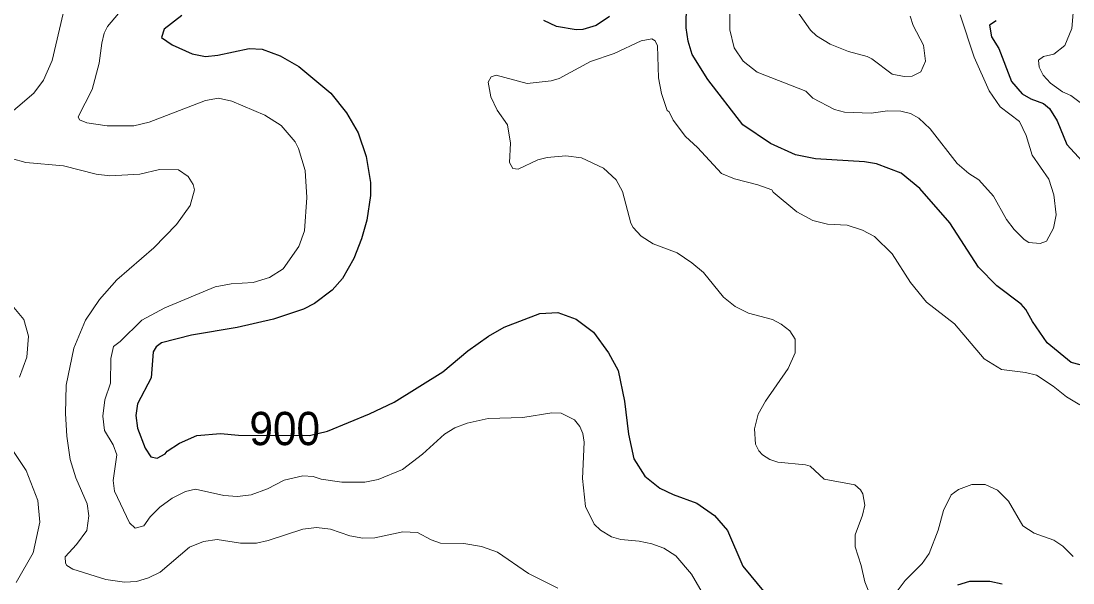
# Model space of a CAD drawing. Extents: x 265 to 291.4, y 7731.5 to 7759.6.
# Drawn here: x 287.145 to 289.671, y 7738.754 to 7740.103 of the extents above; entities that cross this region are included whole.
import ezdxf
from ezdxf.enums import TextEntityAlignment as Align

# ---------------------------------------------------------------- set-up
doc = ezdxf.new("R2010")
doc.units = 0
doc.header["$LTSCALE"] = 0.032
for name, color, linetype, lineweight in [('1', 7, 'Continuous', 25), ('2', 7, 'Continuous', 13), ('61', 7, 'Continuous', 13)]:
    doc.layers.add(name, color=color, linetype=linetype, lineweight=lineweight)

msp = doc.modelspace()

# ---------------------------------------------------------------- linework, layer by layer
at = {"layer": '1'}
for points in [[(289.3759, 7739.619), (289.3035, 7739.701), (289.259, 7739.7383), (289.1993, 7739.7606), (289.1707, 7739.7654), (289.053, 7739.7725), (289.0052, 7739.7821), (288.9448, 7739.8091), (288.8787, 7739.8545), (288.7944, 7739.9627), (288.757, 7740.0231), (288.7475, 7740.055), (288.7427, 7740.0868), (288.7435, 7740.1457)], [(287.5312, 7740.117), (287.489, 7740.0836), (287.4827, 7740.0637), (287.5081, 7740.0462), (287.5559, 7740.0247), (287.5877, 7740.0183), (287.6179, 7740.0215), (287.6927, 7740.0374), (287.7245, 7740.0358), (287.7675, 7740.0199), (287.812, 7739.9945), (287.8891, 7739.9301), (287.9265, 7739.8831), (287.9544, 7739.8354), (287.9743, 7739.7781), (287.9846, 7739.7161), (287.9846, 7739.6843), (287.9759, 7739.6254), (287.9631, 7739.5809), (287.944, 7739.5331), (287.917, 7739.4854), (287.8923, 7739.4575), (287.8502, 7739.4249), (287.8231, 7739.4114), (287.7516, 7739.3875), (287.664, 7739.3676), (287.5543, 7739.3493), (287.4827, 7739.331), (287.4699, 7739.3215), (287.462, 7739.3096), (287.4572, 7739.2468), (287.4246, 7739.1847), (287.4206, 7739.1561), (287.4246, 7739.1258), (287.4429, 7739.0781), (287.4564, 7739.0574), (287.4723, 7739.0542), (287.4914, 7739.0646), (287.4962, 7739.0709), (287.5256, 7739.09), (287.567, 7739.1083), (287.6243, 7739.1131), (287.6672, 7739.1091)], [(288.5581, 7740.1146), (288.5264, 7740.0931), (288.4945, 7740.0828), (288.4786, 7740.082), (288.4309, 7740.0907), (288.4007, 7740.1051)], [(289.4873, 7740.1043), (289.4706, 7740.0939), (289.4761, 7740.0653), (289.4936, 7740.0375), (289.5239, 7739.9579), (289.5493, 7739.9285), (289.57, 7739.9165), (289.6003, 7739.9054), (289.6154, 7739.8935), (289.6336, 7739.8641), (289.6567, 7739.8068), (289.7116, 7739.7471)], [(289.6098, 7739.3311), (289.574, 7739.382), (289.5581, 7739.4106), (289.5469, 7739.4233), (289.4889, 7739.4679), (289.4443, 7739.5124), (289.3759, 7739.619)], [(288.2177, 7739.312), (288.2678, 7739.347), (288.3052, 7739.3684), (288.3911, 7739.4011), (288.4341, 7739.4034), (288.4786, 7739.3875), (288.52, 7739.3565), (288.5558, 7739.3072), (288.5788, 7739.2643), (288.5947, 7739.1911), (288.6043, 7739.1115), (288.617, 7739.0527), (288.6433, 7739.0105), (288.6791, 7738.9818), (288.7109, 7738.9667), (288.7682, 7738.946), (288.8103, 7738.9166), (288.8421, 7738.88), (288.8787, 7738.7949), (288.932, 7738.7297)], [(289.71, 7739.2722), (289.6671, 7739.2833), (289.6098, 7739.3311)], [(287.6672, 7739.1091), (287.8375, 7739.1086), (287.8812, 7739.1186), (287.9822, 7739.16), (288.0411, 7739.1887), (288.158, 7739.261), (288.2177, 7739.312)], [(289.395, 7738.7496), (289.4237, 7738.7583), (289.4714, 7738.7583), (289.5016, 7738.7519)]]:
    msp.add_lwpolyline(points, dxfattribs=at)
at = {"layer": '2'}
for points in [[(287.3252, 7739.736), (287.2472, 7739.7559), (287.1565, 7739.7638), (287.0865, 7739.7829), (287.065, 7739.7956), (287.0547, 7739.8076), (287.0515, 7739.8211), (287.0539, 7739.8274), (287.1756, 7739.9301), (287.1987, 7739.9611), (287.2201, 7740.0088), (287.2464, 7740.1218)], [(287.3793, 7740.1218), (287.353, 7740.09), (287.345, 7740.0741), (287.3387, 7740.0502), (287.3323, 7740.0025), (287.3156, 7739.9388), (287.2822, 7739.8736), (287.2854, 7739.8664), (287.3029, 7739.8593), (287.3522, 7739.8521), (287.4159, 7739.8521), (287.4524, 7739.8609), (287.5877, 7739.9126), (287.6195, 7739.9181), (287.6513, 7739.911), (287.7309, 7739.8776), (287.7698, 7739.8529), (287.8032, 7739.8131), (287.8112, 7739.7972), (287.8271, 7739.7447), (287.8311, 7739.6795), (287.8255, 7739.5999), (287.812, 7739.5618), (287.7746, 7739.5085), (287.742, 7739.4878), (287.7022, 7739.4758), (287.6497, 7739.4727), (287.6115, 7739.4655), (287.4906, 7739.4146), (287.4349, 7739.3852), (287.3832, 7739.3343), (287.3673, 7739.3223), (287.361, 7739.2929), (287.3602, 7739.234)], [(289.2812, 7739.8815), (289.2582, 7739.8871), (289.2264, 7739.8879), (289.1866, 7739.8823), (289.123, 7739.8847), (289.0991, 7739.8911), (289.0466, 7739.9181), (289.0299, 7739.9348), (288.913, 7739.981), (288.8795, 7740.0072), (288.8581, 7740.0391), (288.8477, 7740.082), (288.8477, 7740.1297)], [(289.0108, 7740.125), (289.041, 7740.0812), (289.0553, 7740.0677), (289.088, 7740.0478), (289.1325, 7740.0303), (289.1771, 7740.0184), (289.1882, 7740.0128), (289.2375, 7739.9762), (289.2662, 7739.9706), (289.2852, 7739.9714), (289.3059, 7739.9818), (289.3171, 7740.0072), (289.3123, 7740.0454), (289.2876, 7740.0931), (289.2805, 7740.1154)], [(289.4006, 7740.1186), (289.434, 7740.0168), (289.4698, 7739.9356), (289.4968, 7739.8975), (289.543, 7739.8625), (289.5589, 7739.829), (289.5732, 7739.7813), (289.6138, 7739.724), (289.6257, 7739.6859), (289.6313, 7739.6381), (289.6249, 7739.6063), (289.6082, 7739.5753), (289.5923, 7739.5697), (289.5653, 7739.5721), (289.5541, 7739.5793), (289.5302, 7739.6031), (289.5119, 7739.627), (289.4809, 7739.6827)], [(289.7084, 7739.8927), (289.6663, 7739.9245), (289.6464, 7739.9332), (289.6177, 7739.9539), (289.6002, 7739.9738), (289.5899, 7739.9929), (289.5883, 7740.0096), (289.601, 7740.0184), (289.6257, 7740.0239), (289.652, 7740.0446), (289.6687, 7740.0852), (289.6718, 7740.1234)], [(289.1882, 7738.7154), (289.1715, 7738.7567), (289.1627, 7738.7965), (289.1484, 7738.8411), (289.1484, 7738.8697), (289.1659, 7738.9174), (289.1715, 7738.9413), (289.1667, 7738.9683), (289.1611, 7738.9779), (289.1476, 7738.9898), (289.0736, 7739.0033), (289.0402, 7739.0344), (289.0291, 7739.0383), (288.9623, 7739.0447), (288.9432, 7739.051), (288.9257, 7739.0622), (288.9169, 7739.0717), (288.909, 7739.0877), (288.9066, 7739.1242), (288.9153, 7739.1593), (288.9328, 7739.1911), (288.9877, 7739.269), (289.0044, 7739.3072), (289.0044, 7739.3398), (288.9917, 7739.3597), (288.971, 7739.3756), (288.9496, 7739.3867), (288.8923, 7739.4019), (288.8605, 7739.4178), (288.8318, 7739.4401), (288.7841, 7739.4997), (288.7562, 7739.5228), (288.7205, 7739.5466), (288.6632, 7739.5689), (288.6345, 7739.5872), (288.6154, 7739.6079), (288.6099, 7739.6182), (288.5892, 7739.6938), (288.5741, 7739.7225), (288.5439, 7739.7503), (288.4914, 7739.7749), (288.4532, 7739.7797), (288.4086, 7739.7757), (288.3863, 7739.7702), (288.3386, 7739.7479), (288.3259, 7739.7495), (288.3179, 7739.7638), (288.3203, 7739.81), (288.3131, 7739.8545), (288.2885, 7739.8895), (288.2734, 7739.9213), (288.267, 7739.9563), (288.2742, 7739.9698), (288.2861, 7739.9738), (288.3609, 7739.9531), (288.4182, 7739.9595), (288.4373, 7739.9651), (288.5128, 7740.0064), (288.5693, 7740.0255), (288.6345, 7740.0557), (288.66, 7740.0605), (288.6679, 7740.0558), (288.6735, 7740.0438), (288.6759, 7739.9675)], [(288.6759, 7739.9675), (288.6831, 7739.9293), (288.6966, 7739.8887), (288.7014, 7739.8855), (288.7109, 7739.8656), (288.7411, 7739.8259), (288.7698, 7739.7996)], [(289.4809, 7739.6827), (289.4451, 7739.7224), (289.4213, 7739.7376), (289.3934, 7739.7614), (289.3282, 7739.845), (289.3011, 7739.8704), (289.2812, 7739.8815)], [(288.7698, 7739.7996), (288.827, 7739.7376), (288.8589, 7739.7248), (288.9145, 7739.7105), (288.9479, 7739.6978), (288.9511, 7739.6922), (289.0084, 7739.6453), (289.0466, 7739.6246), (289.0816, 7739.6159), (289.1293, 7739.6135), (289.1659, 7739.6015), (289.1946, 7739.5864), (289.2375, 7739.5443), (289.2813, 7739.4759), (289.3194, 7739.4281), (289.3871, 7739.3764), (289.4579, 7739.2921), (289.5, 7739.2666), (289.5573, 7739.2595), (289.5835, 7739.2531), (289.6241, 7739.2268), (289.6559, 7739.2014), (289.6878, 7739.1823)], [(287.5582, 7739.7113), (287.5463, 7739.7304), (287.5232, 7739.7463), (287.4779, 7739.7471), (287.4302, 7739.736), (287.3586, 7739.732), (287.3252, 7739.736)], [(288.4341, 7738.7416), (288.3641, 7738.7774), (288.2893, 7738.8283), (288.2511, 7738.8418), (288.2082, 7738.849), (288.1525, 7738.8498), (288.1302, 7738.8577), (288.0968, 7738.8752), (288.0618, 7738.8768), (287.995, 7738.8625), (287.9663, 7738.8617), (287.9345, 7738.8673), (287.8884, 7738.8832), (287.855, 7738.8872), (287.8216, 7738.8832), (287.7388, 7738.8562), (287.7102, 7738.8498), (287.672, 7738.8498), (287.6163, 7738.8585), (287.5829, 7738.8538), (287.5495, 7738.8402), (287.4795, 7738.7806), (287.4509, 7738.7663), (287.4222, 7738.7575), (287.3936, 7738.7559), (287.349, 7738.7623), (287.2695, 7738.7877), (287.2552, 7738.7965), (287.252, 7738.8021), (287.2512, 7738.8172), (287.2782, 7738.8466), (287.3029, 7738.88), (287.3077, 7738.9158), (287.3037, 7738.9445), (287.2766, 7739.0065), (287.2631, 7739.0511), (287.2552, 7739.1067), (287.252, 7739.1608), (287.2536, 7739.2293), (287.2719, 7739.3183), (287.2997, 7739.3852), (287.3331, 7739.4345), (287.3753, 7739.4822), (287.4636, 7739.5586), (287.5185, 7739.6151), (287.5511, 7739.6604), (287.5614, 7739.6978), (287.5582, 7739.7113)], [(287.1279, 7739.4154), (287.1517, 7739.3868), (287.1629, 7739.347), (287.1589, 7739.2961), (287.1414, 7739.2483)], [(287.3602, 7739.234), (287.3466, 7739.1943), (287.3411, 7739.1545), (287.3458, 7739.1203), (287.3665, 7739.0861), (287.3753, 7739.0622), (287.3665, 7739.0002)], [(287.3665, 7739.0002), (287.3697, 7738.9747), (287.4055, 7738.8983), (287.419, 7738.8856), (287.4402, 7738.8912), (287.4554, 7738.913), (287.4786, 7738.9362), (287.5081, 7738.958), (287.54, 7738.9739), (287.5638, 7738.9795), (287.6322, 7738.9643), (287.6648, 7738.9619), (287.6975, 7738.9659), (287.7372, 7738.9803), (287.777, 7739.0009), (287.8216, 7739.0113), (287.847, 7739.0097), (287.8661, 7739.0033), (287.9154, 7738.9962), (287.9711, 7738.9962), (288.0029, 7739.0025), (288.061, 7739.0264), (288.1095, 7739.0638), (288.162, 7739.1115), (288.1867, 7739.1266), (288.2161, 7739.1378), (288.267, 7739.1489), (288.3498, 7739.1513), (288.4198, 7739.1624), (288.442, 7739.1616), (288.4739, 7739.1457), (288.4873, 7739.1298), (288.4945, 7739.1131), (288.4977, 7739.0924), (288.4937, 7739.0049), (288.5009, 7738.9381), (288.5216, 7738.8952), (288.5367, 7738.8808), (288.5629, 7738.8649), (288.5852, 7738.8585), (288.6298, 7738.8546), (288.66, 7738.8482), (288.6886, 7738.8379), (288.7173, 7738.8196), (288.7554, 7738.7758), (288.7809, 7738.7313)], [(287.1207, 7739.0797), (287.1573, 7739.024), (287.1852, 7738.9524), (287.1899, 7738.8999), (287.174, 7738.8267), (287.1334, 7738.7551)], [(289.6719, 7738.818), (289.6472, 7738.8426), (289.6257, 7738.8569), (289.578, 7738.8737), (289.5509, 7738.8912), (289.5167, 7738.9508), (289.4905, 7738.9771), (289.4603, 7738.9906), (289.4284, 7738.9906), (289.3966, 7738.9787), (289.3791, 7738.9659), (289.3608, 7738.9286), (289.3481, 7738.8808), (289.3258, 7738.8251), (289.3091, 7738.8013), (289.2685, 7738.7599), (289.2327, 7738.7122)]]:
    msp.add_lwpolyline(points, dxfattribs=at)

# ---------------------------------------------------------------- texts
at = {"layer": '61', "width": 0.95}
msp.add_text('900', height=0.08, dxfattribs=at).set_placement((287.7783, 7739.0851), align=Align.CENTER)

doc.saveas('drawing.dxf')
